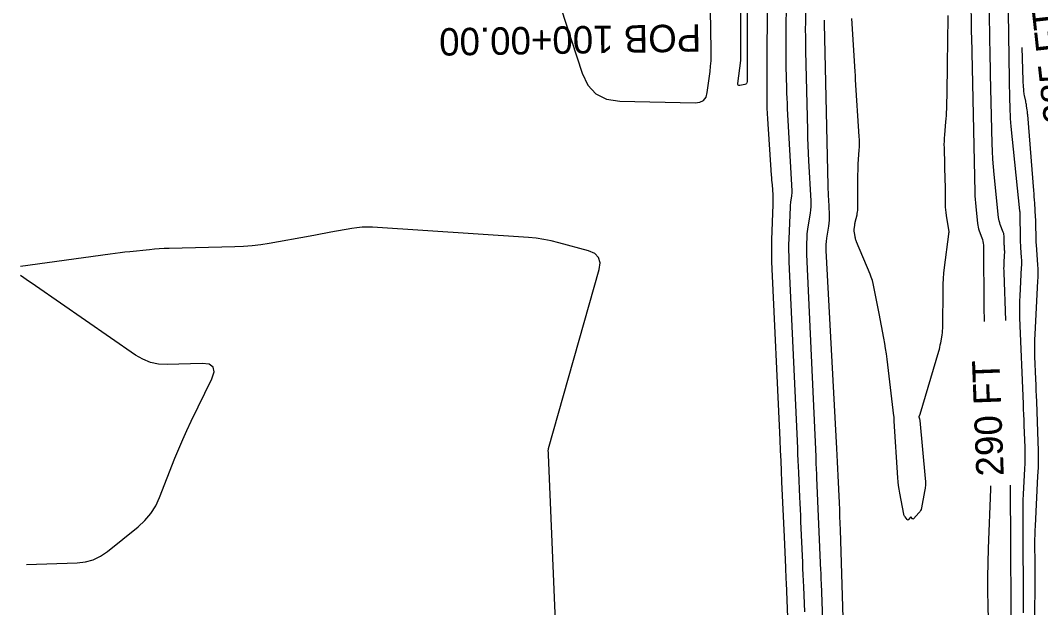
# Model space of a CAD drawing. Extents: x 1768942 to 1774819, y 723037 to 732099.
# Drawn here: x 1770638.6 to 1770861.8, y 724105.6 to 724234 of the extents above; entities that cross this region are included whole.
import ezdxf

# ---------------------------------------------------------------- set-up
doc = ezdxf.new("R2010")
doc.units = 0
for name, color, linetype in [('R_Contour Annot', 7, 'Continuous'), ('R_Contours', 7, 'Continuous'), ('R_Horz Alg Annot', 7, 'Continuous')]:
    doc.layers.add(name, color=color, linetype=linetype)

msp = doc.modelspace()

# ---------------------------------------------------------------- linework, layer by layer
at = {"layer": 'R_Contours'}
for points in [[(1770750.93, 724254.89), (1770761.48, 724222.47), (1770762.72, 724219.84), (1770764.51, 724217.95), (1770766.84, 724216.78), (1770769.71, 724216.34), (1770786.23, 724215.94), (1770787.27, 724216.06), (1770788.06, 724216.48), (1770788.59, 724217.19), (1770788.87, 724218.2), (1770789.48, 724222.83), (1770789.61, 724223.99), (1770789.7, 724225.16), (1770789.75, 724226.32), (1770789.75, 724227.49), (1770789.45, 724245.06)], [(1770797.55, 724250.14), (1770797.6, 724228.6), (1770797.6, 724228.31), (1770797.6, 724228.02), (1770797.6, 724227.72), (1770797.59, 724227.43), (1770797.58, 724226.25), (1770797.58, 724225.95), (1770797.58, 724225.66), (1770797.58, 724225.37), (1770797.58, 724225.07), (1770797.58, 724220.6), (1770797.55, 724220.35), (1770797.45, 724220.16), (1770797.28, 724220.03), (1770797.05, 724219.95), (1770795.98, 724219.75), (1770795.75, 724219.74), (1770795.6, 724219.81), (1770795.52, 724219.95), (1770795.52, 724220.18), (1770796.18, 724225.21), (1770796.21, 724225.5), (1770796.23, 724225.78), (1770796.24, 724226.07), (1770796.24, 724226.36), (1770796.22, 724227.51), (1770796.22, 724227.8), (1770796.22, 724228.09), (1770796.21, 724228.38), (1770796.21, 724228.67), (1770796.18, 724250.31)], [(1770802.06, 724244.71), (1770801.9, 724226.35), (1770801.9, 724225.19), (1770801.89, 724224.03), (1770801.89, 724222.87), (1770801.89, 724221.72), (1770801.89, 724217.08), (1770801.9, 724215.93), (1770801.93, 724214.77), (1770801.98, 724213.61), (1770802.05, 724212.46), (1770802.88, 724200.14), (1770802.91, 724199.6), (1770802.95, 724199.07), (1770802.99, 724198.54), (1770803.03, 724198), (1770803.19, 724195.87), (1770803.22, 724195.34), (1770803.24, 724194.8), (1770803.24, 724194.27), (1770803.23, 724193.74), (1770802.94, 724186), (1770802.9, 724184.8), (1770802.9, 724183.61), (1770802.91, 724182.42), (1770802.95, 724181.22), (1770804.73, 724142.26), (1770804.83, 724139.97), (1770804.93, 724137.69), (1770805.04, 724135.41), (1770805.13, 724133.12), (1770805.66, 724121.09), (1770805.73, 724119.42), (1770805.8, 724117.74), (1770805.95, 724114.39), (1770805.98, 724113.55), (1770806.02, 724112.71), (1770806.05, 724111.87), (1770806.09, 724111.04), (1770806.7, 724095.99)], [(1770810.18, 724104.71), (1770809.97, 724110.11), (1770809.91, 724111.45), (1770809.85, 724112.8), (1770809.8, 724114.15), (1770809.74, 724115.5), (1770809.35, 724124.41), (1770809.3, 724125.74), (1770809.24, 724127.08), (1770809.18, 724128.42), (1770809.12, 724129.76), (1770808.89, 724135.11), (1770808.83, 724136.44), (1770808.77, 724137.78), (1770808.71, 724139.12), (1770808.65, 724140.45), (1770806.8, 724181.19), (1770806.75, 724182.45), (1770806.74, 724183.7), (1770806.74, 724184.95), (1770806.78, 724186.21), (1770807.04, 724193.13), (1770807.05, 724193.43), (1770807.08, 724193.73), (1770807.12, 724194.03), (1770807.16, 724194.33), (1770807.36, 724195.52), (1770807.4, 724195.82), (1770807.42, 724196.12), (1770807.43, 724196.42), (1770807.43, 724196.72), (1770806.45, 724214.66), (1770806.39, 724215.8), (1770806.34, 724216.95), (1770806.3, 724218.09), (1770806.27, 724219.24), (1770806.16, 724223.82), (1770806.14, 724224.97), (1770806.13, 724226.11), (1770806.13, 724227.26), (1770806.13, 724228.41), (1770806.22, 724241.16)], [(1770810.37, 724239.97), (1770810.32, 724233.56), (1770810.31, 724231.97), (1770810.32, 724230.39), (1770810.34, 724228.81), (1770810.37, 724227.22), (1770810.76, 724210), (1770810.8, 724208.31), (1770810.86, 724206.63), (1770810.93, 724204.95), (1770811.02, 724203.27), (1770811.5, 724194.56), (1770811.51, 724193.88), (1770811.5, 724193.2), (1770811.44, 724192.53), (1770811.35, 724191.86), (1770810.84, 724188.83), (1770810.76, 724188.33), (1770810.71, 724187.83), (1770810.66, 724187.33), (1770810.63, 724186.82), (1770810.56, 724184.8), (1770810.55, 724184.3), (1770810.54, 724183.79), (1770810.55, 724183.29), (1770810.57, 724182.78), (1770812.58, 724138.65), (1770812.59, 724138.26), (1770812.61, 724137.87), (1770812.63, 724137.48), (1770812.65, 724137.09), (1770812.75, 724134.75), (1770812.78, 724133.97), (1770813.66, 724113.69), (1770813.68, 724113.29), (1770813.69, 724112.89), (1770813.71, 724112.49), (1770813.73, 724112.09), (1770813.79, 724110.49), (1770813.81, 724110.09), (1770813.82, 724109.69), (1770813.84, 724109.29), (1770813.85, 724108.89), (1770814.58, 724088.63)], [(1770846.5, 724237.05), (1770846.56, 724233.71), (1770846.58, 724232.88), (1770846.59, 724232.05), (1770846.61, 724231.21), (1770846.63, 724230.38), (1770847.4, 724196.35), (1770847.43, 724195.59), (1770847.47, 724194.83), (1770847.53, 724194.07), (1770847.6, 724193.31), (1770847.99, 724189.59), (1770848.04, 724189.18), (1770848.12, 724188.78), (1770848.23, 724188.38), (1770848.37, 724187.99), (1770848.96, 724186.44), (1770849.09, 724186.05), (1770849.18, 724185.66), (1770849.24, 724185.25), (1770849.26, 724184.84), (1770849.39, 724170.97), (1770849.43, 724168.51), (1770849.44, 724168.17)], [(1770841.5, 724235.03), (1770841.42, 724229.08), (1770841.39, 724227.66), (1770841.37, 724226.24), (1770841.35, 724224.82), (1770841.33, 724223.4), (1770841.17, 724214.59), (1770841.15, 724213.88), (1770841.12, 724213.17), (1770841.07, 724212.47), (1770841.01, 724211.77), (1770840.74, 724208.95), (1770840.69, 724208.25), (1770840.65, 724207.54), (1770840.64, 724206.84), (1770840.65, 724206.13), (1770840.85, 724198.72), (1770840.87, 724198.1), (1770840.88, 724197.49), (1770840.89, 724196.87), (1770840.89, 724196.25), (1770840.91, 724193.77), (1770840.93, 724193.16), (1770840.97, 724192.55), (1770841.04, 724191.94), (1770841.13, 724191.33), (1770841.72, 724187.72), (1770841.73, 724187.71), (1770841.73, 724187.7), (1770841.72, 724187.69), (1770841.72, 724187.67), (1770841.71, 724187.63), (1770841.71, 724187.62), (1770841.7, 724187.61), (1770841.7, 724187.6), (1770841.7, 724187.59), (1770841.65, 724187.38), (1770841.64, 724187.34), (1770841.64, 724187.3), (1770841.63, 724187.25), (1770841.62, 724187.21), (1770840.71, 724179.97), (1770840.57, 724178.75), (1770840.47, 724177.52), (1770840.41, 724176.3), (1770840.38, 724175.07), (1770840.32, 724167.09), (1770840.31, 724166.62), (1770840.28, 724166.16), (1770840.23, 724165.7), (1770840.16, 724165.25), (1770839.85, 724163.42), (1770839.77, 724162.97), (1770839.67, 724162.51), (1770839.56, 724162.06), (1770839.43, 724161.62), (1770835.38, 724147.83), (1770835.36, 724147.79), (1770835.34, 724147.74), (1770835.32, 724147.7), (1770835.29, 724147.65), (1770835.19, 724147.48), (1770835.17, 724147.44), (1770835.16, 724147.39), (1770835.16, 724147.34), (1770835.17, 724147.3), (1770835.3, 724146.86), (1770835.32, 724146.77), (1770835.35, 724146.68), (1770835.36, 724146.59), (1770835.37, 724146.5), (1770836.56, 724133.86), (1770836.6, 724133.15), (1770836.59, 724132.43), (1770836.53, 724131.72), (1770836.42, 724131.01), (1770835.71, 724127.38), (1770835.63, 724127.08), (1770835.51, 724126.8), (1770835.36, 724126.54), (1770835.16, 724126.3), (1770834.01, 724125.04), (1770833.95, 724124.99), (1770833.89, 724124.97), (1770833.82, 724124.99), (1770833.76, 724125.04), (1770833.37, 724125.44), (1770832.91, 724124.85), (1770832.83, 724124.77), (1770832.75, 724124.75), (1770832.67, 724124.77), (1770832.59, 724124.85), (1770832.12, 724125.45), (1770832.02, 724125.59), (1770831.95, 724125.74), (1770831.89, 724125.89), (1770831.85, 724126.06), (1770830.99, 724130.64), (1770830.85, 724131.46), (1770830.73, 724132.29), (1770830.64, 724133.12), (1770830.57, 724133.95), (1770829.73, 724146.33), (1770829.72, 724146.43), (1770829.72, 724146.52), (1770829.72, 724146.61), (1770829.73, 724146.71), (1770829.77, 724147.21), (1770829.77, 724147.23), (1770829.76, 724147.26), (1770829.75, 724147.29), (1770829.74, 724147.32), (1770829.68, 724147.42), (1770829.66, 724147.44), (1770829.65, 724147.47), (1770829.64, 724147.5), (1770829.64, 724147.53), (1770828.19, 724159.91), (1770828.04, 724161.07), (1770827.88, 724162.22), (1770827.69, 724163.37), (1770827.49, 724164.51), (1770826.47, 724169.93), (1770826.34, 724170.65), (1770826.2, 724171.38), (1770826.06, 724172.1), (1770825.91, 724172.82), (1770825.33, 724175.71), (1770825.17, 724176.43), (1770824.98, 724177.14), (1770824.74, 724177.83), (1770824.48, 724178.52), (1770821.54, 724185.58), (1770821.5, 724185.67), (1770821.47, 724185.76), (1770821.43, 724185.85), (1770821.4, 724185.95), (1770821.28, 724186.32), (1770821.26, 724186.41), (1770821.23, 724186.5), (1770821.21, 724186.6), (1770821.19, 724186.69), (1770821.05, 724187.59), (1770821.02, 724187.77), (1770821.01, 724187.95), (1770821.01, 724188.14), (1770821.03, 724188.32), (1770821.11, 724189.11), (1770821.14, 724189.31), (1770821.17, 724189.5), (1770821.2, 724189.69), (1770821.25, 724189.88), (1770821.62, 724191.44), (1770821.69, 724191.76), (1770821.74, 724192.09), (1770821.77, 724192.42), (1770821.78, 724192.75), (1770821.81, 724199.57), (1770821.82, 724200.33), (1770821.84, 724201.08), (1770821.87, 724201.83), (1770821.91, 724202.59), (1770822.1, 724205.6), (1770822.13, 724206.35), (1770822.14, 724207.1), (1770822.13, 724207.85), (1770822.1, 724208.6), (1770821.32, 724220.98), (1770821.32, 724221.09), (1770821.31, 724221.2), (1770821.31, 724221.31), (1770821.31, 724221.42), (1770821.32, 724221.93), (1770821.31, 724222.01), (1770821.31, 724222.08), (1770821.3, 724222.16), (1770821.29, 724222.23), (1770821.24, 724222.53), (1770821.22, 724222.6), (1770821.21, 724222.68), (1770821.21, 724222.75), (1770821.2, 724222.83), (1770820.52, 724234.36)], [(1770854.21, 724168.35), (1770853.79, 724178.88), (1770853.78, 724179.33), (1770853.77, 724179.77), (1770853.78, 724180.21), (1770853.8, 724180.66), (1770853.92, 724182.92), (1770853.93, 724183.12), (1770853.93, 724183.32), (1770853.93, 724183.52), (1770853.92, 724183.72), (1770853.86, 724184.52), (1770853.85, 724184.72), (1770853.84, 724184.92), (1770853.83, 724185.12), (1770853.83, 724185.32), (1770853.82, 724186.59), (1770853.81, 724186.87), (1770853.77, 724187.14), (1770853.71, 724187.41), (1770853.62, 724187.67), (1770852.96, 724189.38), (1770852.83, 724189.75), (1770852.73, 724190.13), (1770852.65, 724190.52), (1770852.6, 724190.91), (1770851.62, 724200.27), (1770851.46, 724201.96), (1770851.34, 724203.66), (1770851.25, 724205.36), (1770851.19, 724207.06), (1770850.85, 724222.12), (1770850.81, 724223.9), (1770850.77, 724225.68), (1770850.74, 724227.46), (1770850.7, 724229.24), (1770850.58, 724236.37)], [(1770854.65, 724235.69), (1770854.91, 724221.02), (1770854.93, 724220.17), (1770854.94, 724219.32), (1770854.96, 724218.46), (1770854.98, 724217.61), (1770855.06, 724214.19), (1770855.09, 724213.34), (1770855.13, 724212.49), (1770855.19, 724211.64), (1770855.27, 724210.79), (1770857.2, 724192.35), (1770857.2, 724192.26), (1770857.21, 724192.18), (1770857.22, 724192.09), (1770857.23, 724192.01), (1770857.27, 724191.53), (1770857.27, 724191.5), (1770857.27, 724191.45), (1770857.27, 724191.45), (1770857.27, 724191.44), (1770857.27, 724191.43), (1770857.27, 724191.42), (1770857.31, 724186.5), (1770857.31, 724185.95), (1770857.33, 724185.41), (1770857.36, 724184.86), (1770857.39, 724184.31), (1770857.54, 724182.13), (1770857.57, 724181.58), (1770857.59, 724181.04), (1770857.58, 724180.49), (1770857.56, 724179.94), (1770857.23, 724173.77), (1770857.18, 724172.56), (1770857.15, 724171.35), (1770857.16, 724170.14), (1770857.19, 724168.92), (1770857.94, 724150.16), (1770857.99, 724148.97), (1770858.03, 724147.79), (1770858.08, 724146.6), (1770858.13, 724145.41), (1770858.31, 724140.66), (1770858.34, 724139.47), (1770858.35, 724138.29), (1770858.33, 724137.1), (1770858.28, 724135.91), (1770857.98, 724130.38), (1770857.92, 724129.06), (1770857.88, 724127.74), (1770857.86, 724126.42), (1770857.86, 724125.1), (1770857.98, 724104.49)], [(1770818.67, 724101), (1770817.99, 724122.58), (1770817.94, 724124.06), (1770817.88, 724125.55), (1770817.83, 724127.04), (1770817.77, 724128.52), (1770817.51, 724134.47), (1770817.45, 724135.96), (1770817.38, 724137.45), (1770817.3, 724138.93), (1770817.22, 724140.42), (1770814.87, 724183.68), (1770814.85, 724184.34), (1770814.87, 724185.01), (1770814.93, 724185.67), (1770815.02, 724186.33), (1770815.46, 724188.97), (1770815.55, 724189.63), (1770815.61, 724190.29), (1770815.63, 724190.95), (1770815.61, 724191.62), (1770815.43, 724194.81), (1770815.4, 724195.57), (1770815.36, 724196.32), (1770815.34, 724197.08), (1770815.32, 724197.83), (1770814.51, 724233.31), (1770814.5, 724233.99)], [(1770860.52, 724103.21), (1770860.56, 724111.37), (1770860.57, 724112.38), (1770860.57, 724113.39), (1770860.57, 724114.41), (1770860.56, 724115.42), (1770860.54, 724119.46), (1770860.54, 724120.47), (1770860.56, 724121.48), (1770860.59, 724122.49), (1770860.63, 724123.5), (1770861.21, 724134.37), (1770861.29, 724136.24), (1770861.33, 724138.11), (1770861.32, 724139.99), (1770861.27, 724141.86), (1770860.93, 724150.65), (1770860.88, 724151.87), (1770860.83, 724153.1), (1770860.78, 724154.33), (1770860.73, 724155.56), (1770860.54, 724160.47), (1770860.5, 724161.7), (1770860.5, 724162.92), (1770860.52, 724164.15), (1770860.57, 724165.38), (1770861.2, 724176.97), (1770861.23, 724177.86), (1770861.24, 724178.75), (1770861.22, 724179.65), (1770861.17, 724180.54), (1770860.87, 724184.88), (1770860.83, 724185.39), (1770860.81, 724185.9), (1770860.8, 724186.41), (1770860.79, 724186.92), (1770860.77, 724188.95), (1770860.77, 724189.46), (1770860.75, 724189.97), (1770860.73, 724190.48), (1770860.7, 724190.99), (1770860.5, 724194.04), (1770860.45, 724194.72), (1770860.4, 724195.39), (1770860.35, 724196.07), (1770860.3, 724196.75), (1770858.97, 724213.3), (1770858.95, 724213.56), (1770858.92, 724213.81), (1770858.89, 724214.06), (1770858.85, 724214.31), (1770858.7, 724215.31), (1770858.66, 724215.56), (1770858.61, 724215.81), (1770858.57, 724216.06), (1770858.52, 724216.31), (1770858.27, 724217.54), (1770858.22, 724217.81), (1770858.18, 724218.08), (1770858.14, 724218.35), (1770858.12, 724218.63), (1770858.03, 724219.72), (1770858.01, 724219.99), (1770857.99, 724220.27), (1770857.98, 724220.54), (1770857.97, 724220.82), (1770857.72, 724228.07)], [(1770756.16, 724090.46), (1770754.16, 724138.99), (1770754.15, 724139.1), (1770754.15, 724139.22), (1770754.14, 724139.34), (1770754.13, 724139.46), (1770754.1, 724139.92), (1770754.1, 724140.04), (1770754.11, 724140.16), (1770754.12, 724140.27), (1770754.15, 724140.38), (1770765.21, 724179.5), (1770765.41, 724180.97), (1770765.09, 724182.15), (1770764.24, 724183.03), (1770762.88, 724183.62), (1770756.38, 724185.38), (1770754.75, 724185.77), (1770753.11, 724186.09), (1770751.45, 724186.33), (1770749.78, 724186.48), (1770715.67, 724188.75), (1770714.53, 724188.79), (1770713.38, 724188.76), (1770712.24, 724188.66), (1770711.1, 724188.48), (1770706.56, 724187.64), (1770705.43, 724187.43), (1770704.29, 724187.22), (1770703.16, 724187.02), (1770702.02, 724186.81), (1770693.07, 724185.22), (1770691.2, 724184.92), (1770689.32, 724184.7), (1770687.43, 724184.54), (1770685.53, 724184.46), (1770671.16, 724184.11), (1770670.08, 724184.07), (1770669.01, 724184.01), (1770667.93, 724183.93), (1770666.86, 724183.83), (1770662.56, 724183.4), (1770661.48, 724183.28), (1770660.41, 724183.16), (1770659.34, 724183.02), (1770658.27, 724182.88), (1770638.62, 724180.16)], [(1770639.96, 724115.01), (1770651.07, 724115.4), (1770652.87, 724115.6), (1770654.56, 724116.08), (1770656.16, 724116.83), (1770657.65, 724117.86), (1770664.37, 724123.27), (1770665.86, 724124.64), (1770667.14, 724126.16), (1770668.21, 724127.84), (1770669.07, 724129.68), (1770672.42, 724138.24), (1770673.25, 724140.29), (1770674.12, 724142.33), (1770675.03, 724144.35), (1770675.98, 724146.35), (1770680.5, 724155.63), (1770680.99, 724157.12), (1770680.8, 724158.18), (1770679.92, 724158.79), (1770678.35, 724158.96), (1770670.72, 724158.75), (1770668.86, 724158.84), (1770667.08, 724159.22), (1770665.38, 724159.88), (1770663.77, 724160.82), (1770641.95, 724175.95), (1770641.62, 724176.17), (1770641.29, 724176.4), (1770640.96, 724176.62), (1770640.63, 724176.84), (1770638.64, 724178.18)], [(1770850.82, 724132.2), (1770850.8, 724131.47), (1770850.32, 724118.51), (1770850.22, 724115.39), (1770850.18, 724112.28), (1770850.18, 724109.16), (1770850.23, 724106.04), (1770850.53, 724093.58)], [(1770855.4, 724092.46), (1770855.17, 724132.36)]]:
    msp.add_lwpolyline(points, dxfattribs=at)

# ---------------------------------------------------------------- texts
at = {"layer": 'R_Contour Annot'}
for s, rotation, p in [('285 FT', 96.2962, (1770868.57, 724211.83)), ('290 FT', 92.2038, (1770853.74, 724134.41))]:
    msp.add_text(s, height=6, rotation=rotation, dxfattribs=at).set_placement(p)
at = {"layer": 'R_Horz Alg Annot'}
msp.add_text('POB 100+00.00', height=6, rotation=180.8827, dxfattribs=at).set_placement((1770787.49, 724233.14))

doc.saveas('drawing.dxf')
